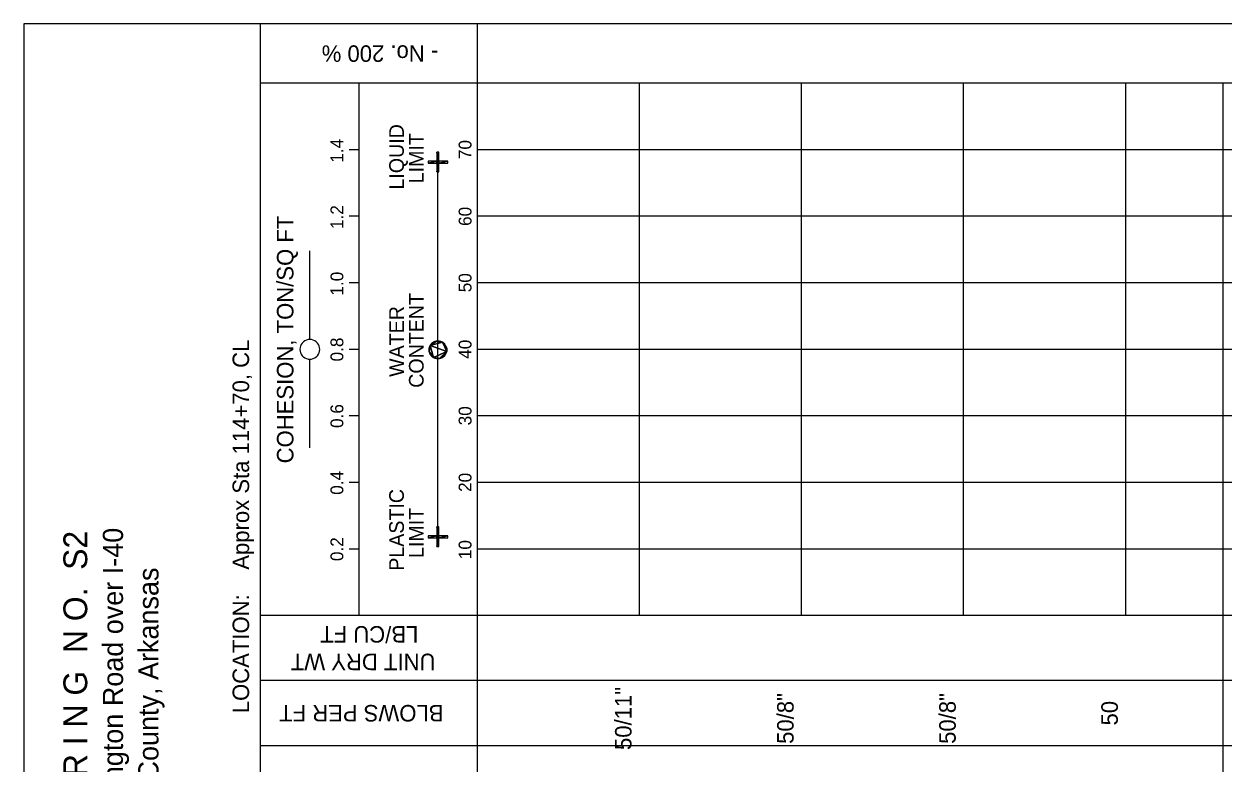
# Model space of a CAD drawing. Extents: x 1313964 to 1316843, y 2087046 to 2096619.
# Drawn here: x 1314075.31 to 1314112.29, y 2089893.52 to 2089916.31 of the extents above; entities that cross this region are included whole.
import ezdxf

# ---------------------------------------------------------------- set-up
doc = ezdxf.new("R2010")
doc.units = 0
doc.layers.add('B-Sub-Contour', color=7, linetype='Continuous')
doc.layers.add('Default', color=7, linetype='Continuous')

# ---------------------------------------------------------------- blocks, each defined once
blk = doc.blocks.new('DMK_7')
at = {"layer": 'Default'}
blk.add_lwpolyline([(0, -15240), (2651.76, -15011.4), (5212.08, -14325.6), (7620, -13197.84), (9799.32, -11673.84), (10774.68, -10774.68), (11673.84, -9799.32), (13197.84, -7620), (14325.6, -5212.08), (15011.4, -2651.76), (15240, 0), (15011.4, 2651.76), (14325.6, 5212.08), (13197.84, 7620), (11673.84, 9799.32), (10774.68, 10774.68), (9799.32, 11673.84), (7620, 13197.84), (5212.08, 14325.6), (2651.76, 15011.4), (0, 15240), (-2651.76, 15011.4), (-5212.08, 14325.6), (-7620, 13197.84), (-9799.32, 11673.84), (-10774.68, 10774.68), (-11673.84, 9799.32), (-13197.84, 7620), (-14325.6, 5212.08), (-15011.4, 2651.76), (-15240, 0), (-15011.4, -2651.76), (-14325.6, -5212.08), (-13197.84, -7620), (-11673.84, -9799.32), (-10774.68, -10774.68), (-9799.32, -11673.84), (-7620, -13197.84), (-5212.08, -14325.6), (-2651.76, -15011.4), (0, -15240)], dxfattribs=at)
blk = doc.blocks.new('DMK_99')
at = {"layer": 'Default'}
for points in [[(-1524, -1524), (-1524, 1524), (-15240, 1524), (-1524, -1524)], [(-1524, -1524), (-15240, 1524), (-15240, -1524), (-1524, -1524)], [(1524, 1524), (1524, 15240), (-1524, 15240), (1524, 1524)], [(1524, 1524), (-1524, 15240), (-1524, 1524), (1524, 1524)], [(-1524, -1524), (1524, -1524), (1524, 1524), (-1524, -1524)], [(-1524, -1524), (1524, 1524), (-1524, 1524), (-1524, -1524)], [(1524, -1524), (15240, -1524), (15240, 1524), (1524, -1524)], [(1524, -1524), (15240, 1524), (1524, 1524), (1524, -1524)], [(-1524, -1524), (-1524, -15240), (1524, -15240), (-1524, -1524)], [(-1524, -1524), (1524, -15240), (1524, -1524), (-1524, -1524)]]:
    blk.add_lwpolyline(points, close=True, dxfattribs=at)
blk = doc.blocks.new('POINT_DISPLAY')
at = {"layer": 'Default'}
blk.add_line((0, 0), (0, 0), dxfattribs=at)
blk = doc.blocks.new('DMK_101')
at = {"layer": 'Default'}
for points in [[(-14269.212, 2386.584), (-14476.476, 0), (-14269.212, -2386.584), (-14269.212, 2386.584)], [(-12638.532, 6858), (-13653.516, 4690.872), (-14269.212, 2386.584), (-12638.532, 6858)], [(-12638.532, 6858), (-14269.212, 2386.584), (-14269.212, -2386.584), (-12638.532, 6858)], [(-12638.532, 6858), (-14269.212, -2386.584), (-3147.06, -13508.736), (-12638.532, 6858)], [(-3147.06, 13511.784), (-7618.476, 11878.056), (-12638.532, 6858), (-3147.06, 13511.784)], [(6097.524, 11878.056), (-3147.06, 13511.784), (-12638.532, 6858), (6097.524, 11878.056)], [(-7618.476, 11878.056), (-11266.932, 8820.912), (-12638.532, 6858), (-7618.476, 11878.056)], [(-3147.06, -13508.736), (6097.524, 11878.056), (-12638.532, 6858), (-3147.06, -13508.736)], [(-7618.476, 11878.056), (-9578.34, 10506.456), (-11266.932, 8820.912), (-7618.476, 11878.056)], [(-9578.34, 10506.456), (-10456.164, 9698.736), (-11266.932, 8820.912), (-9578.34, 10506.456)], [(-3147.06, 13511.784), (-5451.348, 12893.04), (-7618.476, 11878.056), (-3147.06, 13511.784)], [(1626.108, 13511.784), (-760.476, 13712.952), (-3147.06, 13511.784), (1626.108, 13511.784)], [(6097.524, 11878.056), (1626.108, 13511.784), (-3147.06, 13511.784), (6097.524, 11878.056)], [(-3147.06, -13508.736), (11117.58, -6858), (6097.524, 11878.056), (-3147.06, -13508.736)], [(6097.524, 11878.056), (3930.396, 12893.04), (1626.108, 13511.784), (6097.524, 11878.056)], [(11117.58, 6858), (8060.436, 10506.456), (6097.524, 11878.056), (11117.58, 6858)], [(12751.308, 2386.584), (11117.58, 6858), (6097.524, 11878.056), (12751.308, 2386.584)], [(11117.58, -6858), (12751.308, 2386.584), (6097.524, 11878.056), (11117.58, -6858)], [(9745.98, 8820.912), (8938.26, 9698.736), (8060.436, 10506.456), (9745.98, 8820.912)], [(11117.58, 6858), (9745.98, 8820.912), (8060.436, 10506.456), (11117.58, 6858)], [(12751.308, 2386.584), (12132.564, 4690.872), (11117.58, 6858), (12751.308, 2386.584)], [(11117.58, -6858), (12751.308, -2386.584), (12751.308, 2386.584), (11117.58, -6858)], [(12751.308, -2386.584), (12952.476, 0), (12751.308, 2386.584), (12751.308, -2386.584)], [(-14269.212, -2386.584), (-13653.516, -4690.872), (-12638.532, -6858), (-14269.212, -2386.584)], [(-14269.212, -2386.584), (-12638.532, -6858), (-9578.34, -10506.456), (-14269.212, -2386.584)], [(-14269.212, -2386.584), (-9578.34, -10506.456), (-3147.06, -13508.736), (-14269.212, -2386.584)], [(-12638.532, -6858), (-11266.932, -8817.864), (-9578.34, -10506.456), (-12638.532, -6858)], [(-11266.932, -8817.864), (-10456.164, -9695.688), (-9578.34, -10506.456), (-11266.932, -8817.864)], [(-9578.34, -10506.456), (-7618.476, -11878.056), (-3147.06, -13508.736), (-9578.34, -10506.456)], [(-7618.476, -11878.056), (-5451.348, -12893.04), (-3147.06, -13508.736), (-7618.476, -11878.056)], [(-3147.06, -13508.736), (6097.524, -11878.056), (11117.58, -6858), (-3147.06, -13508.736)], [(-3147.06, -13508.736), (1626.108, -13508.736), (6097.524, -11878.056), (-3147.06, -13508.736)], [(-3147.06, -13508.736), (-760.476, -13716), (1626.108, -13508.736), (-3147.06, -13508.736)], [(1626.108, -13508.736), (3930.396, -12893.04), (6097.524, -11878.056), (1626.108, -13508.736)], [(6097.524, -11878.056), (8060.436, -10506.456), (11117.58, -6858), (6097.524, -11878.056)], [(8060.436, -10506.456), (9745.98, -8817.864), (11117.58, -6858), (8060.436, -10506.456)], [(8060.436, -10506.456), (8938.26, -9695.688), (9745.98, -8817.864), (8060.436, -10506.456)], [(11117.58, -6858), (12132.564, -4690.872), (12751.308, -2386.584), (11117.58, -6858)]]:
    blk.add_lwpolyline(points, close=True, dxfattribs=at)
blk.add_blockref('POINT_DISPLAY', (14479.524, 0), dxfattribs=at)

msp = doc.modelspace()

# ---------------------------------------------------------------- linework, layer by layer
at = {"layer": 'B-Sub-Contour'}
for points in [[(1314136.725, 2089873.434), (1314136.725, 2089916.306), (1314075.306, 2089916.306), (1314075.306, 2089873.434), (1314136.725, 2089873.434)], [(1314082.603, 2089873.434), (1314082.603, 2089916.306)], [(1314089.292, 2089873.434), (1314089.292, 2089916.306)], [(1314134.292, 2089914.481), (1314082.603, 2089914.481)], [(1314085.644, 2089914.481), (1314085.34, 2089914.481)], [(1314085.644, 2089898.063), (1314085.644, 2089914.481)], [(1314134.292, 2089914.481), (1314089.292, 2089914.481)], [(1314089.292, 2089898.063), (1314089.292, 2089914.481)], [(1314094.292, 2089898.063), (1314094.292, 2089914.481)], [(1314099.292, 2089898.063), (1314099.292, 2089914.481)], [(1314104.292, 2089898.063), (1314104.292, 2089914.481)], [(1314109.292, 2089898.063), (1314109.292, 2089914.481)], [(1314112.292, 2089894.049), (1314112.292, 2089914.481)], [(1314085.644, 2089912.429), (1314085.34, 2089912.429)], [(1314134.292, 2089912.429), (1314089.292, 2089912.429)], [(1314088.076, 2089900.495), (1314088.076, 2089912.049)], [(1314085.644, 2089910.377), (1314085.34, 2089910.377)], [(1314134.292, 2089910.377), (1314089.292, 2089910.377)], [(1314084.124, 2089906.576), (1314084.124, 2089909.313)], [(1314085.644, 2089908.324), (1314085.34, 2089908.324)], [(1314134.292, 2089908.324), (1314089.292, 2089908.324)], [(1314085.644, 2089906.272), (1314085.34, 2089906.272)], [(1314134.292, 2089906.272), (1314089.292, 2089906.272)], [(1314084.124, 2089903.232), (1314084.124, 2089905.968)], [(1314085.644, 2089904.22), (1314085.34, 2089904.22)], [(1314134.292, 2089904.22), (1314089.292, 2089904.22)], [(1314085.644, 2089902.167), (1314085.34, 2089902.167)], [(1314134.292, 2089902.167), (1314089.292, 2089902.167)], [(1314085.644, 2089900.115), (1314085.34, 2089900.115)], [(1314134.292, 2089900.115), (1314089.292, 2089900.115)], [(1314134.292, 2089898.063), (1314082.603, 2089898.063)], [(1314085.644, 2089898.063), (1314085.34, 2089898.063)], [(1314134.292, 2089898.063), (1314089.292, 2089898.063)], [(1314134.292, 2089896.056), (1314082.603, 2089896.056)], [(1314134.292, 2089894.049), (1314082.603, 2089894.049)], [(1314112.292, 2089878.178), (1314112.292, 2089894.049)]]:
    msp.add_lwpolyline(points, dxfattribs=at)

# ---------------------------------------------------------------- block references
at = {"layer": 'B-Sub-Contour', "xscale": 1.9951013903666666e-05, "yscale": 1.9951013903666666e-05, "rotation": 90}
for name, p in [('DMK_99', (1314088.076, 2089912.049)), ('DMK_7', (1314084.124, 2089906.272)), ('DMK_101', (1314088.076, 2089906.272)), ('DMK_99', (1314088.076, 2089900.495))]:
    msp.add_blockref(name, p, dxfattribs=at)

# ---------------------------------------------------------------- texts
at = {"layer": 'B-Sub-Contour'}
for s, height, rotation, p in [('- No. 200 %', 0.50899, 180, (1314088.084, 2089915.648)), ('LIQUID', 0.4524, 90, (1314087.025, 2089911.2)), ('LIMIT', 0.4524, 90, (1314087.634, 2089911.394)), ('1.4', 0.3959, 90, (1314085.157, 2089912.028)), ('70', 0.3959, 90, (1314089.11, 2089912.138)), ('1.2', 0.3959, 90, (1314085.157, 2089909.983)), ('60', 0.3959, 90, (1314089.11, 2089910.078)), ('COHESION, TON/SQ FT', 0.50899, 90, (1314083.618, 2089902.756)), ('1.0', 0.3959, 90, (1314085.157, 2089907.93)), ('50', 0.3959, 90, (1314089.11, 2089908.033)), ('CONTENT', 0.4524, 90, (1314087.634, 2089905.087)), ('WATER', 0.4524, 90, (1314087.025, 2089905.423)), ('0.8', 0.3959, 90, (1314085.157, 2089905.9)), ('LOCATION:    Approx Sta 114+70, CL', 0.50899, 90, (1314082.25, 2089895.052)), ('40', 0.3959, 90, (1314089.11, 2089905.981)), ('0.6', 0.3959, 90, (1314085.157, 2089903.848)), ('30', 0.3959, 90, (1314089.11, 2089903.929)), ('0.4', 0.3959, 90, (1314085.157, 2089901.788)), ('20', 0.3959, 90, (1314089.11, 2089901.876)), ('PLASTIC', 0.4524, 90, (1314087.025, 2089899.445)), ('LIMIT', 0.4524, 90, (1314087.634, 2089899.84)), ('061610 - Remington Road over I-40', 0.62209, 90, (1314078.361, 2089887.499)), ('L O G  O F  B O R I N G  N O.  S2', 0.7352, 90, (1314077.257, 2089885.763)), ('0.2', 0.3959, 90, (1314085.157, 2089899.743)), ('10', 0.3959, 90, (1314089.11, 2089899.802)), ('Lonoke County, Arkansas', 0.62209, 90, (1314079.455, 2089890.018)), ('LB/CU FT', 0.509, 180, (1314087.47, 2089897.739)), ('UNIT DRY WT', 0.50899, 180, (1314087.999, 2089896.888)), ('50/11"', 0.509, 90, (1314094.047, 2089893.918)), ('50/8"', 0.509, 90, (1314099.047, 2089894.107)), ('50/8"', 0.509, 90, (1314104.047, 2089894.107)), ('BLOWS PER FT', 0.50899, 180, (1314088.245, 2089895.307)), ('50', 0.509, 90, (1314109.047, 2089894.674))]:
    msp.add_text(s, height=height, rotation=rotation, dxfattribs=at).set_placement(p)

doc.saveas('drawing.dxf')
